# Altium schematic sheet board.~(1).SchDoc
size A2
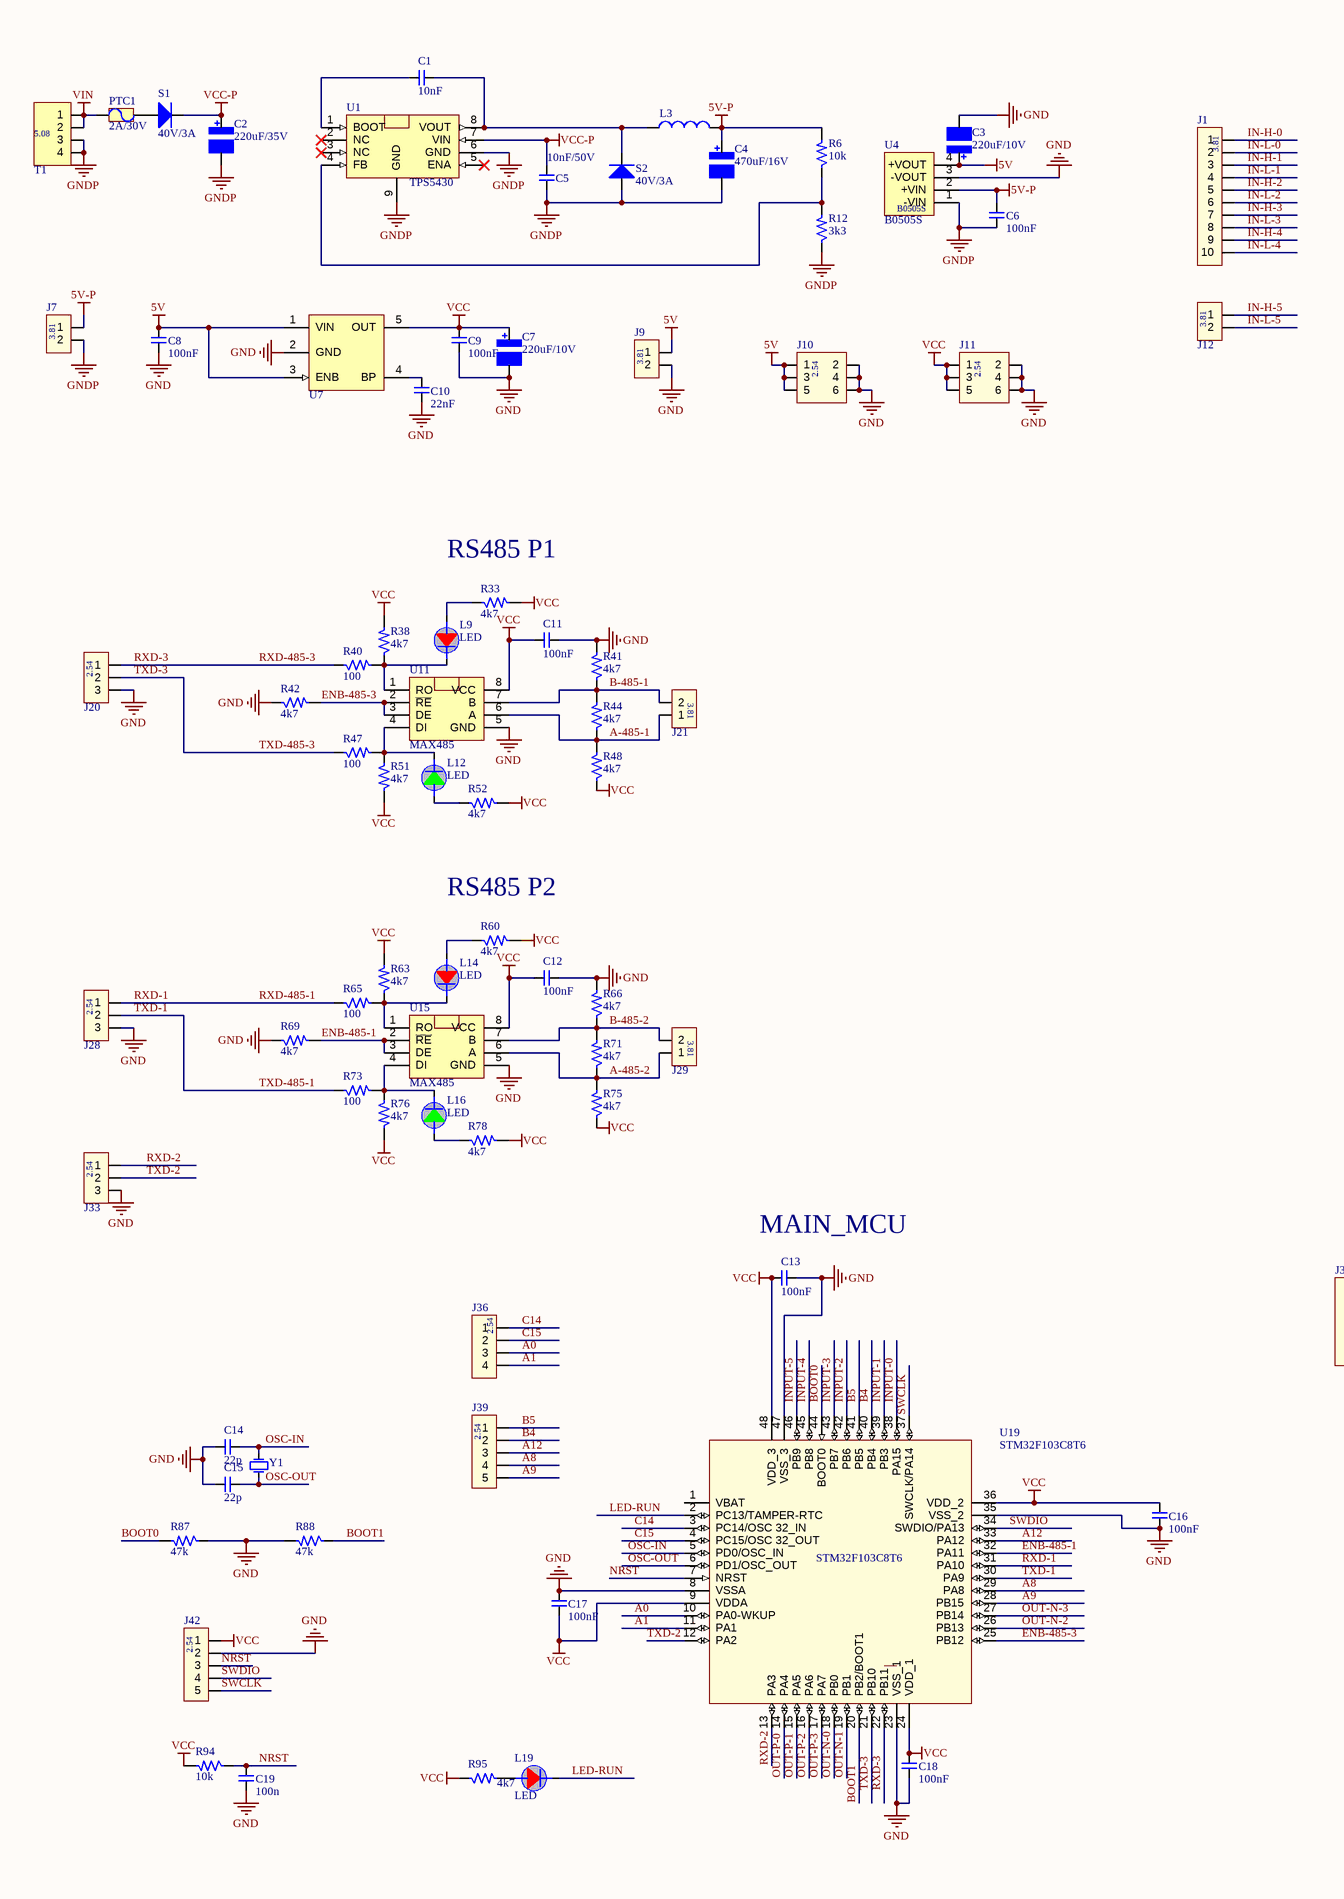
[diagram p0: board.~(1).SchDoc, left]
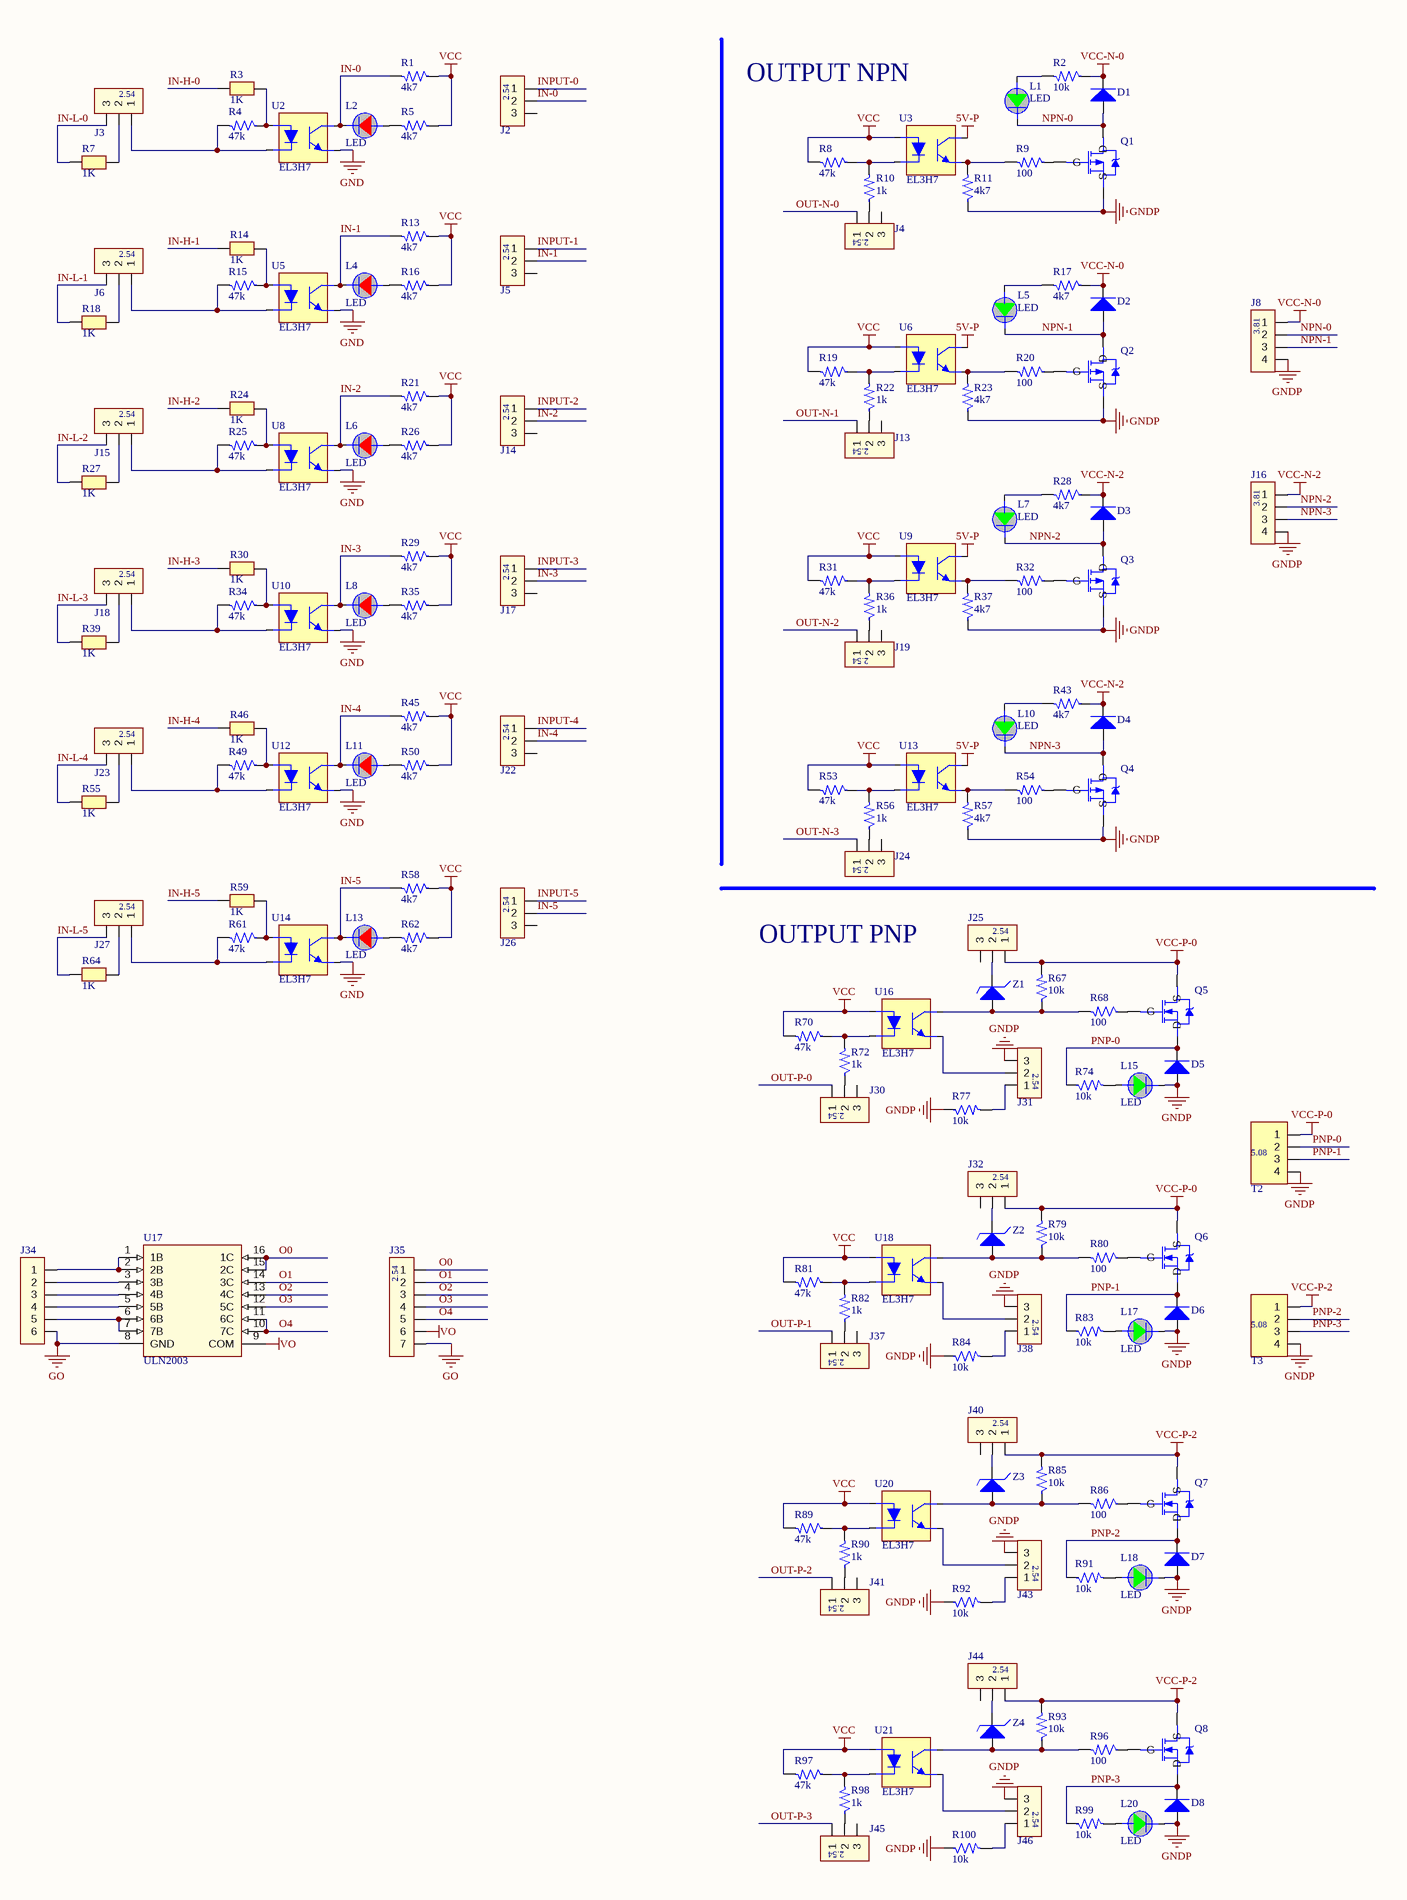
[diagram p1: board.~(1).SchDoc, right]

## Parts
C1  10nF  [Capacitor 0603]
C2  220uF/35V  [Capacitor ALU 8x10mm]
C3  220uF/10V  [Capacitor ALU 6.3x7.7mm]
C4  470uF/16V  [Capacitor ALU 8x10mm]
C5  10nF/50V  [Capacitor 0603]
C6  100nF  [Capacitor 0603]
C7  220uF/10V  [Capacitor ALU 6.3x7.7mm]
C8  100nF  [Capacitor 0603]
C9  100nF  [Capacitor 0603]
C10  22nF  [Capacitor 0603]
C11  100nF  [Capacitor 0603]
C12  100nF  [Capacitor 0603]
C13  100nF  [Capacitor 0603]
C14  22p  [Capacitor 0603]
C15  22p  [Capacitor 0603]
C16  100nF  [Capacitor 0603]
C17  100nF  [Capacitor 0603]
C18  100nF  [Capacitor 0603]
C19  100n  [Capacitor 0603]
D1  (no value)  [DIODE SS24 SMA]
D2  (no value)  [DIODE SS24 SMA]
D3  (no value)  [DIODE SS24 SMA]
D4  (no value)  [DIODE SS24 SMA]
D5  (no value)  [DIODE SS24 SMA]
D6  (no value)  [DIODE SS24 SMA]
D7  (no value)  [DIODE SS24 SMA]
D8  (no value)  [DIODE SS24 SMA]
J1  15EDG3.8 10P RA  [15EDG3.81 10P RA]  (value not drawn)
J2  jump 2.54mm 3p  [JUMP 2.54MM 3P]  (value not drawn)
J3  jump 2.54mm 3p  [JUMP 2.54MM 3P]  (value not drawn)
J4  jump 2.54mm 3p  [JUMP 2.54MM 3P]  (value not drawn)
J5  jump 2.54mm 3p  [JUMP 2.54MM 3P]  (value not drawn)
J6  jump 2.54mm 3p  [JUMP 2.54MM 3P]  (value not drawn)
J7  15EDG3.81 2P RA  [15EDG3.81 2P RA]  (value not drawn)
J8  15EDG3.81 4P RA  [15EDG3.81 4P RA]  (value not drawn)
J9  15EDG3.81 2P RA  [15EDG3.81 2P RA]  (value not drawn)
J10  jump 2.54mm 2x3p  [JUMP 2.54MM 2X3P]  (value not drawn)
J11  jump 2.54mm 2x3p  [JUMP 2.54MM 2X3P]  (value not drawn)
J12  15EDG3.81 2P RA  [15EDG3.81 2P RA]  (value not drawn)
J13  jump 2.54mm 3p  [JUMP 2.54MM 3P]  (value not drawn)
J14  jump 2.54mm 3p  [JUMP 2.54MM 3P]  (value not drawn)
J15  jump 2.54mm 3p  [JUMP 2.54MM 3P]  (value not drawn)
J16  15EDG3.81 4P RA  [15EDG3.81 4P RA]  (value not drawn)
J17  jump 2.54mm 3p  [JUMP 2.54MM 3P]  (value not drawn)
J18  jump 2.54mm 3p  [JUMP 2.54MM 3P]  (value not drawn)
J19  jump 2.54mm 3p  [JUMP 2.54MM 3P]  (value not drawn)
J20  jump 2.54mm 3p  [JUMP 2.54MM 3P]  (value not drawn)
J21  15EDG3.81 2P RA  [15EDG3.81 2P RA]  (value not drawn)
J22  jump 2.54mm 3p  [JUMP 2.54MM 3P]  (value not drawn)
J23  jump 2.54mm 3p  [JUMP 2.54MM 3P]  (value not drawn)
J24  jump 2.54mm 3p  [JUMP 2.54MM 3P]  (value not drawn)
J25  jump 2.54mm 3p  [JUMP 2.54MM 3P]  (value not drawn)
J26  jump 2.54mm 3p  [JUMP 2.54MM 3P]  (value not drawn)
J27  jump 2.54mm 3p  [JUMP 2.54MM 3P]  (value not drawn)
J28  jump 2.54mm 3p  [JUMP 2.54MM 3P]  (value not drawn)
J29  15EDG3.81 2P RA  [15EDG3.81 2P RA]  (value not drawn)
J30  jump 2.54mm 3p  [JUMP 2.54MM 3P]  (value not drawn)
J31  jump 2.54mm 3p  [JUMP 2.54MM 3P]  (value not drawn)
J32  jump 2.54mm 3p  [JUMP 2.54MM 3P]  (value not drawn)
J33  jump 2.54mm 3p  [JUMP 2.54MM 3P]  (value not drawn)
J34  jump 2.54mm 6p  [JUMP 2.54MM 6P]  (value not drawn)
J35  jump 2.54mm 7p  [JUMP 2.54MM 7P]  (value not drawn)
J36  jump 2.54mm 4p  [JUMP 2.54MM 4P]  (value not drawn)
J37  jump 2.54mm 3p  [JUMP 2.54MM 3P]  (value not drawn)
J38  jump 2.54mm 3p  [JUMP 2.54MM 3P]  (value not drawn)
J39  jump 2.54mm 5p  [JUMP 2.54MM 5P]  (value not drawn)
J40  jump 2.54mm 3p  [JUMP 2.54MM 3P]  (value not drawn)
J41  jump 2.54mm 3p  [JUMP 2.54MM 3P]  (value not drawn)
J42  jump 2.54mm 5p  [JUMP 2.54MM 5P]  (value not drawn)
J43  jump 2.54mm 3p  [JUMP 2.54MM 3P]  (value not drawn)
J44  jump 2.54mm 3p  [JUMP 2.54MM 3P]  (value not drawn)
J45  jump 2.54mm 3p  [JUMP 2.54MM 3P]  (value not drawn)
J46  jump 2.54mm 3p  [JUMP 2.54MM 3P]  (value not drawn)
L1  LED  [LED GREEN 0603 SMD]
L2  LED  [LED RED 0603 SMD]
L3  33uH  [INDUCTOR SMD 10x10x4mm]  (value not drawn)
L4  LED  [LED RED 0603 SMD]
L5  LED  [LED GREEN 0603 SMD]
L6  LED  [LED RED 0603 SMD]
L7  LED  [LED GREEN 0603 SMD]
L8  LED  [LED RED 0603 SMD]
L9  LED  [LED RED 0603 SMD]
L10  LED  [LED GREEN 0603 SMD]
L11  LED  [LED RED 0603 SMD]
L12  LED  [LED GREEN 0603 SMD]
L13  LED  [LED RED 0603 SMD]
L14  LED  [LED RED 0603 SMD]
L15  LED  [LED GREEN 0603 SMD]
L16  LED  [LED GREEN 0603 SMD]
L17  LED  [LED GREEN 0603 SMD]
L18  LED  [LED GREEN 0603 SMD]
L19  LED  [LED RED 0603 SMD]
L20  LED  [LED GREEN 0603 SMD]
PTC1  2A/30V  [PTC DIP]
Q1  MOSFET N  [AO3401 Mosfet P SOT23]  (value not drawn)
Q2  MOSFET N  [AO3401 Mosfet P SOT23]  (value not drawn)
Q3  MOSFET N  [AO3401 Mosfet P SOT23]  (value not drawn)
Q4  MOSFET N  [AO3401 Mosfet P SOT23]  (value not drawn)
Q5  MOSFET P  [AO3401 Mosfet P SOT23]  (value not drawn)
Q6  MOSFET P  [AO3401 Mosfet P SOT23]  (value not drawn)
Q7  MOSFET P  [AO3401 Mosfet P SOT23]  (value not drawn)
Q8  MOSFET P  [AO3401 Mosfet P SOT23]  (value not drawn)
R1  4k7  [RES 0603]
R2  10k  [RES 0603]
R3  1K  [RESISTOR 1206]
R4  47k  [RES 0603]
R5  4k7  [RES 0603]
R6  10k  [RES 0603]
R7  1K  [RESISTOR 1206]
R8  47k  [RES 0603]
R9  100  [RES 0603]
R10  1k  [RES 0603]
R11  4k7  [RES 0603]
R12  3k3  [RES 0603]
R13  4k7  [RES 0603]
R14  1K  [RESISTOR 1206]
R15  47k  [RES 0603]
R16  4k7  [RES 0603]
R17  4k7  [RES 0603]
R18  1K  [RESISTOR 1206]
R19  47k  [RES 0603]
R20  100  [RES 0603]
R21  4k7  [RES 0603]
R22  1k  [RES 0603]
R23  4k7  [RES 0603]
R24  1K  [RESISTOR 1206]
R25  47k  [RES 0603]
R26  4k7  [RES 0603]
R27  1K  [RESISTOR 1206]
R28  4k7  [RES 0603]
R29  4k7  [RES 0603]
R30  1K  [RESISTOR 1206]
R31  47k  [RES 0603]
R32  100  [RES 0603]
R33  4k7  [RES 0603]
R34  47k  [RES 0603]
R35  4k7  [RES 0603]
R36  1k  [RES 0603]
R37  4k7  [RES 0603]
R38  4k7  [RES 0603]
R39  1K  [RESISTOR 1206]
R40  100  [RES 0603]
R41  4k7  [RES 0603]
R42  4k7  [RES 0603]
R43  4k7  [RES 0603]
R44  4k7  [RES 0603]
R45  4k7  [RES 0603]
R46  1K  [RESISTOR 1206]
R47  100  [RES 0603]
R48  4k7  [RES 0603]
R49  47k  [RES 0603]
R50  4k7  [RES 0603]
R51  4k7  [RES 0603]
R52  4k7  [RES 0603]
R53  47k  [RES 0603]
R54  100  [RES 0603]
R55  1K  [RESISTOR 1206]
R56  1k  [RES 0603]
R57  4k7  [RES 0603]
R58  4k7  [RES 0603]
R59  1K  [RESISTOR 1206]
R60  4k7  [RES 0603]
R61  47k  [RES 0603]
R62  4k7  [RES 0603]
R63  4k7  [RES 0603]
R64  1K  [RESISTOR 1206]
R65  100  [RES 0603]
R66  4k7  [RES 0603]
R67  10k  [RES 0603]
R68  100  [RES 0603]
R69  4k7  [RES 0603]
R70  47k  [RES 0603]
R71  4k7  [RES 0603]
R72  1k  [RES 0603]
R73  100  [RES 0603]
R74  10k  [RES 0603]
R75  4k7  [RES 0603]
R76  4k7  [RES 0603]
R77  10k  [RES 0603]
R78  4k7  [RES 0603]
R79  10k  [RES 0603]
R80  100  [RES 0603]
R81  47k  [RES 0603]
R82  1k  [RES 0603]
R83  10k  [RES 0603]
R84  10k  [RES 0603]
R85  10k  [RES 0603]
R86  100  [RES 0603]
R87  47k  [RES 0603]
R88  47k  [RES 0603]
R89  47k  [RES 0603]
R90  1k  [RES 0603]
R91  10k  [RES 0603]
R92  10k  [RES 0603]
R93  10k  [RES 0603]
R94  10k  [RES 0603]
R95  4k7  [RES 0603]
R96  100  [RES 0603]
R97  47k  [RES 0603]
R98  1k  [RES 0603]
R99  10k  [RES 0603]
R100  10k  [RES 0603]
S1  40V/3A  [DIODE SS24 SMB]
S2  40V/3A  [DIODE SS24 SMB]
T1  (no value)  [2EDG5.08 4P RA]
T2  (no value)  [2EDG5.08 4P RA]
T3  (no value)  [2EDG5.08 4P RA]
U1  TPS5430  [SOP8 - PAD - VIA]
U2  EL3H7  [SSOP4]
U3  EL3H7  [SSOP4]
U4  B0505S  [B0505S]
U5  EL3H7  [SSOP4]
U6  EL3H7  [SSOP4]
U7  RT9193-33GB  [RT9193]  (value not drawn)
U8  EL3H7  [SSOP4]
U9  EL3H7  [SSOP4]
U10  EL3H7  [SSOP4]
U11  MAX485  [SOP8]
U12  EL3H7  [SSOP4]
U13  EL3H7  [SSOP4]
U14  EL3H7  [SSOP4]
U15  MAX485  [SOP8]
U16  EL3H7  [SSOP4]
U17  ULN2003  [SOP16]
U18  EL3H7  [SSOP4]
U19  STM32F103C8T6  [LQFP48]
U20  EL3H7  [SSOP4]
U21  EL3H7  [SSOP4]
Y1  (no value)  [Crystal SMD 5032]
Z1  BZT52C3V3  [DIODE SOD-123]  (value not drawn)
Z2  BZT52C3V3  [DIODE SOD-123]  (value not drawn)
Z3  BZT52C3V3  [DIODE SOD-123]  (value not drawn)
Z4  BZT52C3V3  [DIODE SOD-123]  (value not drawn)

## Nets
5V: C3.2 C8.2 J9.1 J10.1 J10.3 J10.5 U4.4(+VOUT) U7.1(VIN) U7.3(ENB)
5V-P: C4.2 C6.2 J7.1 L3.2 R6.2 U3.4 U4.2(+VIN) U6.4 U9.4 U13.4
GND: C3.1 C7.1 C8.1 C9.1 C10.1 C11.1 C12.1 C13.2 C14.1 C15.1 C16.1 C17.1 C18.2 C19.1 J9.2 J10.2 J10.4 J10.6 J11.2 J11.4 J11.6 J20.3 J28.3 J33.3 J42.2 R41.2 R42.1 R66.2 R69.1 R87.1 R88.2 U2.3 U4.3(-VOUT) U5.3 U7.2(GND) U8.3 U10.3 U11.5(GND) U12.3 U14.3 U15.5(GND) U19.8(VSSA) U19.23(VSS_1) U19.35(VSS_2) U19.47(VSS_3)
GNDP: C2.1 C4.1 C5.1 C6.1 D5.1(A) D6.1(A) D7.1(A) D8.1(A) J7.2 J8.4 J16.4 J31.3 J38.3 J43.3 J46.3 L15.2(Katot) L17.2(Katot) L18.2(Katot) L20.2(Katot) Q1.2(S) Q2.2(S) Q3.2(S) Q4.2(S) R11.1 R12.1 R23.1 R37.1 R57.1 R77.1 R84.1 R92.1 R100.1 S2.1(A) T1.3 T1.4 T2.4 T3.4 U1.6(GND) U1.9(GND) U4.1(-VIN)
GO: J34.6 J35.7 U17.8(GND)
VCC: C7.2 C9.2 C11.2 C12.2 C13.1 C16.2 C17.2 C18.1 J11.1 J11.3 J11.5 J42.1 R1.1 R5.1 R8.2 R13.1 R16.1 R19.2 R21.1 R26.1 R29.1 R31.2 R33.2 R35.1 R38.2 R45.1 R48.1 R50.1 R51.2 R52.2 R53.2 R58.1 R60.2 R62.1 R63.2 R70.2 R75.1 R76.2 R78.2 R81.2 R89.2 R94.2 R95.1 R97.2 U3.1 U6.1 U7.5(OUT) U9.1 U11.8(VCC) U13.1 U15.8(VCC) U16.1 U18.1 U19.9(VDDA) U19.24(VDD_1) U19.36(VDD_2) U19.48(VDD_3) U20.1 U21.1
VCC-N-0: D1.2(K) D2.2(K) J8.1 R2.1 R17.1
VCC-N-2: D3.2(K) D4.2(K) J16.1 R28.1 R43.1
VCC-P: C2.2 C5.2 S1.2(K) U1.7(VIN)
VCC-P-0: J25.1 J32.1 Q5.1(S) Q6.1(S) R67.2 R79.2 T2.1
VCC-P-2: J40.1 J44.1 Q7.1(S) Q8.1(S) R85.2 R93.2 T3.1
VIN: PTC1.1 T1.1 T1.2
VO: J35.6 U17.9(COM)
A0: J36.3 U19.10(PA0-WKUP)
A1: J36.4 U19.11(PA1)
A8: J39.4 U19.29(PA8)
A9: J39.5 U19.28(PB15)
A12: J39.3 U19.33(PA12)
A-485-1: J21.1 R44.1 R48.2 U11.6(A)
A-485-2: J29.1 R71.1 R75.2 U15.6(A)
B4: J39.2 U19.40(PB4)
B5: J39.1 U19.41(PB5)
B-485-1: J21.2 R41.1 R44.2 U11.7(B)
B-485-2: J29.2 R66.1 R71.2 U15.7(B)
BOOT0: R87.2 U19.44(BOOT0)
BOOT1: R88.1 U19.20(PB2/BOOT1)
C14: J36.1 U19.3(PC14/OSC_32_IN)
C15: J36.2 U19.4(PC15/OSC_32_OUT)
ENB-485-1: R69.2 U15.2(~{RE}) U15.3(DE) U19.32(PA11)
ENB-485-3: R42.2 U11.2(~{RE}) U11.3(DE) U19.25(PB12)
IN-0: J2.2 L2.2(Katot) R1.2 U2.4
IN-1: J5.2 L4.2(Katot) R13.2 U5.4
IN-2: J14.2 L6.2(Katot) R21.2 U8.4
IN-3: J17.2 L8.2(Katot) R29.2 U10.4
IN-4: J22.2 L11.2(Katot) R45.2 U12.4
IN-5: J26.2 L13.2(Katot) R58.2 U14.4
IN-H-0: J1.1 R3.1
IN-H-1: J1.3 R14.1
IN-H-2: J1.5 R24.1
IN-H-3: J1.7 R30.1
IN-H-4: J1.9 R46.1
IN-H-5: J12.1 R59.1
IN-L-0: J1.2 J3.3 R7.1
IN-L-1: J1.4 J6.3 R18.1
IN-L-2: J1.6 J15.3 R27.1
IN-L-3: J1.8 J18.3 R39.1
IN-L-4: J1.10 J23.3 R55.1
IN-L-5: J12.2 J27.3 R64.1
INPUT-0: J2.1 U19.38(PA15)
INPUT-1: J5.1 U19.39(PB3)
INPUT-2: J14.1 U19.42(PB6)
INPUT-3: J17.1 U19.43(PB7)
INPUT-4: J22.1 U19.45(PB8)
INPUT-5: J26.1 U19.46(PB9)
LED-RUN: L19.2(Katot) U19.2(PC13/TAMPER-RTC)
NPN-0: D1.1(A) J8.2 L1.2(Katot) Q1.1(D)
NPN-1: D2.1(A) J8.3 L5.2(Katot) Q2.1(D)
NPN-2: D3.1(A) J16.2 L7.2(Katot) Q3.1(D)
NPN-3: D4.1(A) J16.3 L10.2(Katot) Q4.1(D)
NRST: C19.2 J42.3 R94.1 U19.7(NRST)
O0: J35.1 U17.15(2C) U17.16(1C)
O1: J35.2 U17.14(3C)
O2: J35.3 U17.13(4C)
O3: J35.4 U17.12(5C)
O4: J35.5 U17.10(7C) U17.11(6C)
OSC-IN: C14.2 U19.5(PD0/OSC_IN) Y1.2(OSC2)
OSC-OUT: C15.2 U19.6(PD1/OSC_OUT) Y1.1(OSC1)
OUT-N-0: J4.1 U19.18(PB0)
OUT-N-1: J13.1 U19.19(PB1)
OUT-N-2: J19.1 U19.26(PB13)
OUT-N-3: J24.1 U19.27(PB14)
OUT-P-0: J30.1 U19.14(PA4)
OUT-P-1: J37.1 U19.15(PA5)
OUT-P-2: J41.1 U19.16(PA6)
OUT-P-3: J45.1 U19.17(PA7)
PNP-0: D5.2(K) Q5.2(D) R74.1 T2.2
PNP-1: D6.2(K) Q6.2(D) R83.1 T2.3
PNP-2: D7.2(K) Q7.2(D) R91.1 T3.2
PNP-3: D8.2(K) Q8.2(D) R99.1 T3.3
RXD-1: J28.1 R65.1 U19.31(PA10)  [also labelled RXD-485-1]
RXD-2: J33.1 U19.13(PA3)
RXD-3: J20.1 R40.1 U19.22(PB11)  [also labelled RXD-485-3]
SWCLK: J42.5 U19.37(SWCLK/PA14)
SWDIO: J42.4 U19.34(SWDIO/PA13)
TXD-1: J28.2 R73.1 U19.30(PA9)  [also labelled TXD-485-1]
TXD-2: J33.2 U19.12(PA2)
TXD-3: J20.2 R47.1 U19.21(PB10)  [also labelled TXD-485-3]
NetC1_1: C1.1 L3.1 S2.2(K) U1.8(VOUT)
NetC1_2: C1.2 U1.1(BOOT)
NetC10_2: C10.2 U7.4(BP)
NetJ3_1: J3.1 R4.2 U2.2
NetJ3_2: J3.2 R7.2
NetJ4_2: J4.2 R10.1
NetJ6_1: J6.1 R15.2 U5.2
NetJ6_2: J6.2 R18.2
NetJ13_2: J13.2 R22.1
NetJ15_1: J15.1 R25.2 U8.2
NetJ15_2: J15.2 R27.2
NetJ18_1: J18.1 R34.2 U10.2
NetJ18_2: J18.2 R39.2
NetJ19_2: J19.2 R36.1
NetJ23_1: J23.1 R49.2 U12.2
NetJ23_2: J23.2 R55.2
NetJ24_2: J24.2 R56.1
NetJ25_2: J25.2 Z1.2(K)
NetJ27_1: J27.1 R61.2 U14.2
NetJ27_2: J27.2 R64.2
NetJ30_2: J30.2 R72.1
NetJ31_1: J31.1 R77.2
NetJ31_2: J31.2 U16.3
NetJ32_2: J32.2 Z2.2(K)
NetJ34_1: J34.1 U17.1(1B) U17.2(2B)
NetJ34_2: J34.2 U17.3(3B)
NetJ34_3: J34.3 U17.4(4B)
NetJ34_4: J34.4 U17.5(5B)
NetJ34_5: J34.5 U17.6(6B) U17.7(7B)
NetJ37_2: J37.2 R82.1
NetJ38_1: J38.1 R84.2
NetJ38_2: J38.2 U18.3
NetJ40_2: J40.2 Z3.2(K)
NetJ41_2: J41.2 R90.1
NetJ43_1: J43.1 R92.2
NetJ43_2: J43.2 U20.3
NetJ44_2: J44.2 Z4.2(K)
NetJ45_2: J45.2 R98.1
NetJ46_1: J46.1 R100.2
NetJ46_2: J46.2 U21.3
NetL1_1: L1.1(anot) R2.2
NetL2_1: L2.1(anot) R5.2
NetL4_1: L4.1(anot) R16.2
NetL5_1: L5.1(anot) R17.2
NetL6_1: L6.1(anot) R26.2
NetL7_1: L7.1(anot) R28.2
NetL8_1: L8.1(anot) R35.2
NetL9_1: L9.1(anot) R33.1
NetL9_2: L9.2(Katot) R38.1 R40.2 U11.1(RO)
NetL10_1: L10.1(anot) R43.2
NetL11_1: L11.1(anot) R50.2
NetL12_1: L12.1(anot) R52.1
NetL12_2: L12.2(Katot) R47.2 R51.1 U11.4(DI)
NetL13_1: L13.1(anot) R62.2
NetL14_1: L14.1(anot) R60.1
NetL14_2: L14.2(Katot) R63.1 R65.2 U15.1(RO)
NetL15_1: L15.1(anot) R74.2
NetL16_1: L16.1(anot) R78.1
NetL16_2: L16.2(Katot) R73.2 R76.1 U15.4(DI)
NetL17_1: L17.1(anot) R83.2
NetL18_1: L18.1(anot) R91.2
NetL19_1: L19.1(anot) R95.2
NetL20_1: L20.1(anot) R99.2
NetPTC1_2: PTC1.2 S1.1(A)
NetQ1_3: Q1.3(G) R9.1
NetQ2_3: Q2.3(G) R20.1
NetQ3_3: Q3.3(G) R32.1
NetQ4_3: Q4.3(G) R54.1
NetQ5_3: Q5.3(G) R68.1
NetQ6_3: Q6.3(G) R80.1
NetQ7_3: Q7.3(G) R86.1
NetQ8_3: Q8.3(G) R96.1
NetR3_2: R3.2 R4.1 U2.1
NetR6_1: R6.1 R12.2 U1.4(FB)
NetR8_1: R8.1 R10.2 U3.2
NetR9_2: R9.2 R11.2 U3.3
NetR14_2: R14.2 R15.1 U5.1
NetR19_1: R19.1 R22.2 U6.2
NetR20_2: R20.2 R23.2 U6.3
NetR24_2: R24.2 R25.1 U8.1
NetR30_2: R30.2 R34.1 U10.1
NetR31_1: R31.1 R36.2 U9.2
NetR32_2: R32.2 R37.2 U9.3
NetR46_2: R46.2 R49.1 U12.1
NetR53_1: R53.1 R56.2 U13.2
NetR54_2: R54.2 R57.2 U13.3
NetR59_2: R59.2 R61.1 U14.1
NetR67_1: R67.1 R68.2 U16.4 Z1.1(A)
NetR70_1: R70.1 R72.2 U16.2
NetR79_1: R79.1 R80.2 U18.4 Z2.1(A)
NetR81_1: R81.1 R82.2 U18.2
NetR85_1: R85.1 R86.2 U20.4 Z3.1(A)
NetR89_1: R89.1 R90.2 U20.2
NetR93_1: R93.1 R96.2 U21.4 Z4.1(A)
NetR97_1: R97.1 R98.2 U21.2

Not connected (* = marked no-connect by the designer): J2 3; J4 3; J5 3; J13 3; J14 3; J17 3; J19 3; J22 3; J24 3; J25 3; J26 3; J30 3; J32 3; J37 3; J40 3; J41 3; J44 3; J45 3; U1 2(NC)* 3(NC)* 5(ENA)*; U19 1(VBAT)

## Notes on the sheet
- OUTPUT NPN
- RS485 P1
- RS485 P2
- OUTPUT PNP
- (near C13) MAIN_MCU

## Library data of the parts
C1 C5 C6 C8-C19 = Capacitor 0603: Value: 10u
C2 C4 = capacitor aluminum smd 8x10mm
C3 C7 = capacitor aluminum smd 6.3x7.7mm
D1-D8 = diode SMA
L1 L5 L7 L10 L12 L15-L18 L20 = LED GREEN SMD
L2 L4 L6 L8 L9 L11 L13 L14 L19 = LED RED SMD
L3 = INDUCTOR SMD 10x10x4mm
PTC1 = PTC DIP: Value: 10k
Q1-Q4 = MOSFET N AO3402
Q5-Q8 = MOSFET P AO3401
R1 R2 R4-R6 R8-R13 R15-R17 R19-R23 R25 R26 R28 R29 R31-R38 R40-R45 R47-R54 R56-R58 R60-R63 R65-R100 = res
R3 R7 R14 R18 R24 R27 R30 R39 R46 R55 R59 R64 = resistor 1206
S1 S2 = diode SMB
T1-T3 = 2EDG5.08 4P RA
Y1 = Crystal 8MHZ SMD 5032
Z1-Z4 = diode Zenner BZT52C3V3 SOD-123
